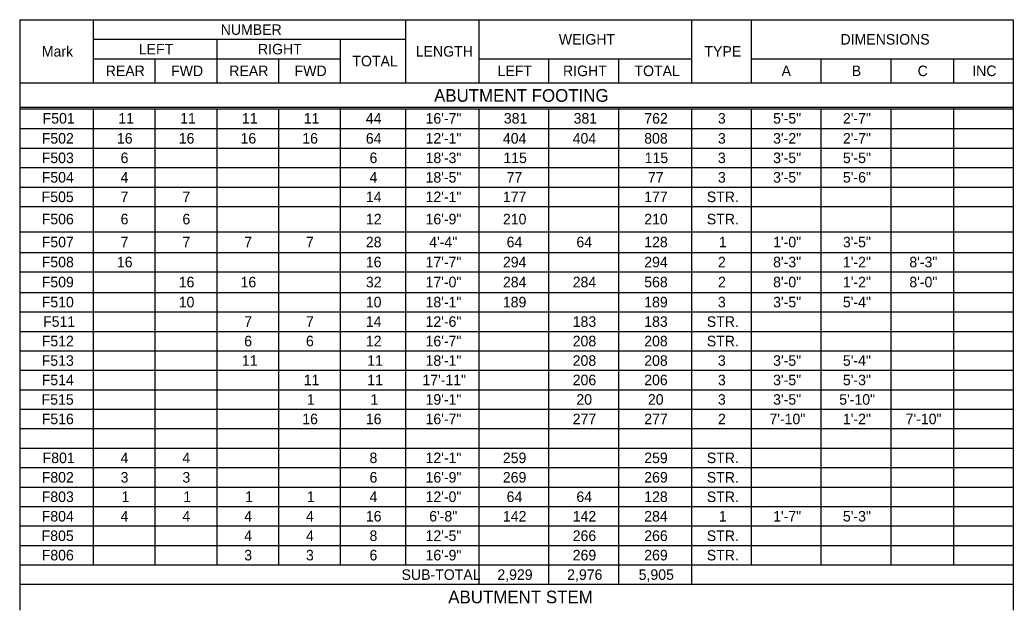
# Model space of a CAD drawing. Extents: x -16.6 to 33.3, y -8.6 to 39.2.
# Drawn here: x 1.87 to 15.08, y 12.96 to 20.75 of the extents above; entities that cross this region are included whole.
import ezdxf

# ---------------------------------------------------------------- set-up
doc = ezdxf.new("R2010")
doc.units = 0
doc.layers.add('BR_X_Beam_Centerline', color=7, linetype='Continuous')
doc.layers.add('Default', color=7, linetype='Continuous')

msp = doc.modelspace()

# ---------------------------------------------------------------- linework, layer by layer
at = {"layer": 'Default'}
for p, q in [((1.873, 20.752), (15.081, 20.752)), ((1.873, 20.752), (1.873, 19.571)), ((2.847, 20.752), (2.847, 19.916)), ((7.001, 20.752), (7.001, 19.916)), ((7.975, 20.752), (7.975, 19.916)), ((10.806, 20.752), (10.806, 19.916)), ((11.597, 20.752), (11.597, 19.916)), ((15.081, 20.752), (15.081, 19.571)), ((2.847, 20.494), (7.001, 20.494)), ((4.491, 20.494), (4.491, 19.916)), ((6.134, 20.494), (6.134, 19.916)), ((2.847, 20.235), (6.134, 20.235)), ((3.669, 20.235), (3.669, 19.916)), ((5.312, 20.235), (5.312, 19.916)), ((7.975, 20.235), (10.806, 20.235)), ((8.903, 20.235), (8.903, 19.916)), ((9.832, 20.235), (9.832, 19.916)), ((11.597, 20.235), (15.081, 20.235)), ((12.525, 20.235), (12.525, 19.916)), ((13.453, 20.235), (13.453, 19.916)), ((14.29, 20.235), (14.29, 19.916)), ((1.873, 19.916), (15.081, 19.916)), ((1.873, 19.591), (15.081, 19.591)), ((1.873, 19.591), (1.873, 12.906)), ((1.873, 19.571), (15.081, 19.571)), ((2.847, 19.571), (2.847, 13.509)), ((3.669, 19.571), (3.669, 13.509)), ((4.491, 19.571), (4.491, 13.509)), ((5.312, 19.571), (5.312, 13.509)), ((6.134, 19.591), (6.134, 13.509)), ((7.001, 19.571), (7.001, 13.509)), ((7.975, 19.571), (7.975, 13.251)), ((8.903, 19.571), (8.903, 13.251)), ((9.832, 19.591), (9.832, 13.251)), ((10.806, 19.571), (10.806, 13.251)), ((11.597, 19.571), (11.597, 13.509)), ((12.525, 19.571), (12.525, 13.509)), ((13.453, 19.571), (13.453, 13.509)), ((14.29, 19.591), (14.29, 13.509)), ((15.081, 19.591), (15.081, 12.906)), ((1.873, 19.307), (15.081, 19.307)), ((1.873, 19.048), (15.081, 19.048)), ((1.873, 18.789), (15.081, 18.789)), ((1.873, 18.531), (15.081, 18.531)), ((1.873, 18.272), (15.081, 18.272)), ((1.873, 17.937), (15.081, 17.937)), ((1.873, 17.663), (15.081, 17.663)), ((1.873, 17.405), (15.081, 17.405)), ((1.873, 17.131), (15.081, 17.131)), ((1.873, 16.872), (15.081, 16.872)), ((1.873, 16.613), (15.081, 16.613)), ((1.873, 16.355), (15.081, 16.355)), ((1.873, 16.096), (15.081, 16.096)), ((1.873, 15.837), (15.081, 15.837)), ((1.873, 15.579), (15.081, 15.579)), ((1.873, 15.32), (15.081, 15.32)), ((1.873, 15.061), (15.081, 15.061)), ((1.873, 14.803), (15.081, 14.803)), ((1.873, 14.544), (15.081, 14.544)), ((1.873, 14.285), (15.081, 14.285)), ((1.873, 14.027), (15.081, 14.027)), ((1.873, 13.768), (15.081, 13.768)), ((1.873, 13.509), (15.081, 13.509)), ((1.873, 13.251), (15.081, 13.251))]:
    msp.add_line(p, q, dxfattribs=at)

# ---------------------------------------------------------------- texts
at = {"layer": 'BR_X_Beam_Centerline'}
for s, height, p in [('NUMBER', 0.14, (4.544, 20.553)), ('WEIGHT', 0.14, (9.04, 20.424)), ('DIMENSIONS', 0.14, (12.786, 20.424)), ('Mark', 0.14, (2.165, 20.264)), ('LEFT', 0.14, (3.455, 20.294)), ('RIGHT', 0.14, (5.04, 20.294)), ('LENGTH', 0.14, (7.138, 20.264)), ('TYPE', 0.14, (10.976, 20.264)), ('TOTAL', 0.14, (6.295, 20.135)), ('REAR', 0.14, (3.015, 20.005)), ('FWD', 0.14, (3.884, 20.005)), ('REAR', 0.14, (4.658, 20.005)), ('FWD', 0.14, (5.527, 20.005)), ('LEFT', 0.14, (8.226, 20.005)), ('RIGHT', 0.14, (9.096, 20.005)), ('TOTAL', 0.14, (10.046, 20.005)), ('A', 0.14, (12.002, 20.005)), ('B', 0.14, (12.935, 20.005)), ('C', 0.14, (13.812, 20.005)), ('INC', 0.14, (14.538, 20.005)), ('ABUTMENT FOOTING', 0.16799, (7.381, 19.664)), ('F501', 0.14, (2.176, 19.374)), ('11', 0.14, (3.183, 19.374)), ('11', 0.14, (4.005, 19.374)), ('11', 0.14, (4.826, 19.374)), ('11', 0.14, (5.648, 19.374)), ('44', 0.14, (6.474, 19.374)), ('16\'-7"', 0.14, (7.268, 19.374)), ('381', 0.14, (8.309, 19.374)), ('381', 0.14, (9.237, 19.374)), ('762', 0.14, (10.177, 19.374)), ('3', 0.14, (11.156, 19.374)), ('5\'-5"', 0.14, (11.89, 19.374)), ('2\'-7"', 0.14, (12.818, 19.374)), ('F502', 0.14, (2.164, 19.108)), ('16', 0.14, (3.164, 19.108)), ('16', 0.14, (3.986, 19.108)), ('16', 0.14, (4.808, 19.108)), ('16', 0.14, (5.629, 19.108)), ('64', 0.14, (6.474, 19.108)), ('12\'-1"', 0.14, (7.268, 19.108)), ('404', 0.14, (8.297, 19.108)), ('404', 0.14, (9.225, 19.108)), ('808', 0.14, (10.176, 19.108)), ('3', 0.14, (11.156, 19.108)), ('3\'-2"', 0.14, (11.89, 19.108)), ('2\'-7"', 0.14, (12.818, 19.108)), ('F503', 0.14, (2.164, 18.849)), ('6', 0.14, (3.213, 18.849)), ('6', 0.14, (6.523, 18.849)), ('18\'-3"', 0.14, (7.268, 18.849)), ('115', 0.14, (8.303, 18.849)), ('115', 0.14, (10.182, 18.849)), ('3', 0.14, (11.156, 18.849)), ('3\'-5"', 0.14, (11.89, 18.849)), ('5\'-5"', 0.14, (12.818, 18.849)), ('F504', 0.14, (2.164, 18.59)), ('4', 0.14, (3.213, 18.59)), ('4', 0.14, (6.523, 18.59)), ('18\'-5"', 0.14, (7.268, 18.59)), ('77', 0.14, (8.346, 18.59)), ('77', 0.14, (10.225, 18.59)), ('3', 0.14, (11.156, 18.59)), ('3\'-5"', 0.14, (11.89, 18.59)), ('5\'-6"', 0.14, (12.818, 18.59)), ('F505', 0.14, (2.163, 18.331)), ('7', 0.14, (3.213, 18.331)), ('7', 0.14, (4.035, 18.331)), ('14', 0.14, (6.474, 18.331)), ('12\'-1"', 0.14, (7.268, 18.331)), ('177', 0.14, (8.297, 18.331)), ('177', 0.14, (10.176, 18.331)), ('STR.', 0.14, (11.008, 18.331)), ('F506', 0.14, (2.164, 18.035)), ('6', 0.14, (3.213, 18.035)), ('6', 0.14, (4.035, 18.035)), ('12', 0.14, (6.475, 18.035)), ('16\'-9"', 0.14, (7.268, 18.035)), ('210', 0.14, (8.297, 18.035)), ('210', 0.14, (10.176, 18.035)), ('STR.', 0.14, (11.008, 18.035)), ('F507', 0.14, (2.164, 17.73)), ('7', 0.14, (3.213, 17.73)), ('7', 0.14, (4.035, 17.73)), ('7', 0.14, (4.857, 17.73)), ('7', 0.14, (5.678, 17.73)), ('28', 0.14, (6.474, 17.73)), ('4\'-4"', 0.14, (7.317, 17.73)), ('64', 0.14, (8.346, 17.73)), ('64', 0.14, (9.274, 17.73)), ('128', 0.14, (10.176, 17.73)), ('1', 0.14, (11.168, 17.73)), ('1\'-0"', 0.14, (11.89, 17.73)), ('3\'-5"', 0.14, (12.818, 17.73)), ('F508', 0.14, (2.164, 17.464)), ('16', 0.14, (3.164, 17.464)), ('16', 0.14, (6.474, 17.464)), ('17\'-7"', 0.14, (7.268, 17.464)), ('294', 0.14, (8.297, 17.464)), ('294', 0.14, (10.176, 17.464)), ('2', 0.14, (11.157, 17.464)), ('8\'-3"', 0.14, (11.89, 17.464)), ('1\'-2"', 0.14, (12.818, 17.464)), ('8\'-3"', 0.14, (13.701, 17.464)), ('F509', 0.14, (2.164, 17.198)), ('16', 0.14, (3.986, 17.198)), ('16', 0.14, (4.808, 17.198)), ('32', 0.14, (6.475, 17.198)), ('17\'-0"', 0.14, (7.268, 17.198)), ('284', 0.14, (8.297, 17.198)), ('284', 0.14, (9.225, 17.198)), ('568', 0.14, (10.176, 17.198)), ('2', 0.14, (11.157, 17.198)), ('8\'-0"', 0.14, (11.89, 17.198)), ('1\'-2"', 0.14, (12.818, 17.198)), ('8\'-0"', 0.14, (13.701, 17.198)), ('F510', 0.14, (2.164, 16.932)), ('10', 0.14, (3.986, 16.932)), ('10', 0.14, (6.474, 16.932)), ('18\'-1"', 0.14, (7.268, 16.932)), ('189', 0.14, (8.296, 16.932)), ('189', 0.14, (10.176, 16.932)), ('3', 0.14, (11.156, 16.932)), ('3\'-5"', 0.14, (11.89, 16.932)), ('5\'-4"', 0.14, (12.818, 16.932)), ('F511', 0.14, (2.182, 16.673)), ('7', 0.14, (4.857, 16.673)), ('7', 0.14, (5.678, 16.673)), ('14', 0.14, (6.474, 16.673)), ('12\'-6"', 0.14, (7.268, 16.673)), ('183', 0.14, (9.225, 16.673)), ('183', 0.14, (10.176, 16.673)), ('STR.', 0.14, (11.008, 16.673)), ('F512', 0.14, (2.164, 16.414)), ('6', 0.14, (4.857, 16.414)), ('6', 0.14, (5.678, 16.414)), ('12', 0.14, (6.475, 16.414)), ('16\'-7"', 0.14, (7.268, 16.414)), ('208', 0.14, (9.225, 16.414)), ('208', 0.14, (10.176, 16.414)), ('STR.', 0.14, (11.008, 16.414)), ('F513', 0.14, (2.164, 16.155)), ('11', 0.14, (4.826, 16.155)), ('11', 0.14, (6.493, 16.155)), ('18\'-1"', 0.14, (7.268, 16.155)), ('208', 0.14, (9.225, 16.155)), ('208', 0.14, (10.176, 16.155)), ('3', 0.14, (11.156, 16.155)), ('3\'-5"', 0.14, (11.89, 16.155)), ('5\'-4"', 0.14, (12.818, 16.155)), ('F514', 0.14, (2.164, 15.897)), ('11', 0.14, (5.648, 15.897)), ('11', 0.14, (6.493, 15.897)), ('17\'-11"', 0.14, (7.226, 15.897)), ('206', 0.14, (9.225, 15.897)), ('206', 0.14, (10.176, 15.897)), ('3', 0.14, (11.156, 15.897)), ('3\'-5"', 0.14, (11.89, 15.897)), ('5\'-3"', 0.14, (12.818, 15.897)), ('F515', 0.14, (2.163, 15.638)), ('1', 0.14, (5.69, 15.638)), ('1', 0.14, (6.535, 15.638)), ('19\'-1"', 0.14, (7.268, 15.638)), ('20', 0.14, (9.274, 15.638)), ('20', 0.14, (10.225, 15.638)), ('3', 0.14, (11.156, 15.638)), ('3\'-5"', 0.14, (11.89, 15.638)), ('5\'-10"', 0.14, (12.769, 15.638)), ('F516', 0.14, (2.164, 15.379)), ('16', 0.14, (5.629, 15.379)), ('16', 0.14, (6.474, 15.379)), ('16\'-7"', 0.14, (7.268, 15.379)), ('277', 0.14, (9.225, 15.379)), ('277', 0.14, (10.176, 15.379)), ('2', 0.14, (11.157, 15.379)), ('7\'-10"', 0.14, (11.841, 15.379)), ('1\'-2"', 0.14, (12.818, 15.379)), ('7\'-10"', 0.14, (13.652, 15.379)), ('F801', 0.14, (2.176, 14.862)), ('4', 0.14, (3.213, 14.862)), ('4', 0.14, (4.035, 14.862)), ('8', 0.14, (6.523, 14.862)), ('12\'-1"', 0.14, (7.268, 14.862)), ('259', 0.14, (8.296, 14.862)), ('259', 0.14, (10.176, 14.862)), ('STR.', 0.14, (11.008, 14.862)), ('F802', 0.14, (2.164, 14.603)), ('3', 0.14, (3.213, 14.603)), ('3', 0.14, (4.035, 14.603)), ('6', 0.14, (6.523, 14.603)), ('16\'-9"', 0.14, (7.268, 14.603)), ('269', 0.14, (8.296, 14.603)), ('269', 0.14, (10.176, 14.603)), ('STR.', 0.14, (11.008, 14.603)), ('F803', 0.14, (2.164, 14.345)), ('1', 0.14, (3.225, 14.345)), ('1', 0.14, (4.047, 14.345)), ('1', 0.14, (4.869, 14.345)), ('1', 0.14, (5.69, 14.345)), ('4', 0.14, (6.523, 14.345)), ('12\'-0"', 0.14, (7.268, 14.345)), ('64', 0.14, (8.346, 14.345)), ('64', 0.14, (9.274, 14.345)), ('128', 0.14, (10.176, 14.345)), ('STR.', 0.14, (11.008, 14.345)), ('F804', 0.14, (2.164, 14.086)), ('4', 0.14, (3.213, 14.086)), ('4', 0.14, (4.035, 14.086)), ('4', 0.14, (4.857, 14.086)), ('4', 0.14, (5.679, 14.086)), ('16', 0.14, (6.474, 14.086)), ('6\'-8"', 0.14, (7.317, 14.086)), ('142', 0.14, (8.297, 14.086)), ('142', 0.14, (9.225, 14.086)), ('284', 0.14, (10.176, 14.086)), ('1', 0.14, (11.168, 14.086)), ('1\'-7"', 0.14, (11.89, 14.086)), ('5\'-3"', 0.14, (12.818, 14.086)), ('F805', 0.14, (2.163, 13.827)), ('4', 0.14, (4.857, 13.827)), ('4', 0.14, (5.679, 13.827)), ('8', 0.14, (6.523, 13.827)), ('12\'-5"', 0.14, (7.268, 13.827)), ('266', 0.14, (9.225, 13.827)), ('266', 0.14, (10.176, 13.827)), ('STR.', 0.14, (11.008, 13.827)), ('F806', 0.14, (2.164, 13.569)), ('3', 0.14, (4.857, 13.569)), ('3', 0.14, (5.678, 13.569)), ('6', 0.14, (6.523, 13.569)), ('16\'-9"', 0.14, (7.268, 13.569)), ('269', 0.14, (9.225, 13.569)), ('269', 0.14, (10.176, 13.569)), ('STR.', 0.14, (11.008, 13.569)), ('SUB-TOTAL', 0.14, (6.949, 13.31)), ('2,929', 0.14, (8.223, 13.31)), ('2,976', 0.14, (9.151, 13.31)), ('5,905', 0.14, (10.102, 13.31)), ('ABUTMENT STEM', 0.16799, (7.57, 12.999))]:
    msp.add_text(s, height=height, dxfattribs=at).set_placement(p)

doc.saveas('drawing.dxf')
